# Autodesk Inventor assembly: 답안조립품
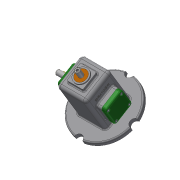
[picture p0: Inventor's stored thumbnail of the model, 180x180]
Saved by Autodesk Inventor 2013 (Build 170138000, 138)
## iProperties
Created: 2018-07
Part Number: 답안조립품
Document SubType Name: Assembly
Designer: dgall
Author: dgall
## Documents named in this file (16)
- C:\Users\dgall\Desktop\480707V1015\답안조립품.iam
- C:\Users\dgall\Desktop\480707V1015\V벨트풀리.ipt
- C:\Users\dgall\Desktop\480707V1015\고정핀 1.2x8.ipt
- C:\Users\dgall\Desktop\480707V1015\뒤커버.ipt
- C:\Users\dgall\Desktop\480707V1015\링크.ipt
- C:\Users\dgall\Desktop\480707V1015\멈춤나사 M3x8.ipt
- C:\Users\dgall\Desktop\480707V1015\베어링 12x32x10.ipt
- C:\Users\dgall\Desktop\480707V1015\본체.ipt
- C:\Users\dgall\Desktop\480707V1015\볼트 M4.ipt
- C:\Users\dgall\Desktop\480707V1015\부시.ipt
- C:\Users\dgall\Desktop\480707V1015\슬라이드.ipt
- C:\Users\dgall\Desktop\480707V1015\앞커버.ipt
- C:\Users\dgall\Desktop\480707V1015\오일 실 12 25 7.ipt
- C:\Users\dgall\Desktop\480707V1015\키 4x4x10.ipt
- C:\Users\dgall\Desktop\480707V1015\편심축.ipt
- C:\Users\dgall\Desktop\480707V1015\핀 5x18.ipt
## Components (3 placed, 3 different names)
1. V벨트풀리:1 — 각도:2
2. 고정핀 1.2x8:1
3. 핀 5x18:1
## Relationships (1: Angle 1)
- 각도:2 [Angle]: V벨트풀리:1
